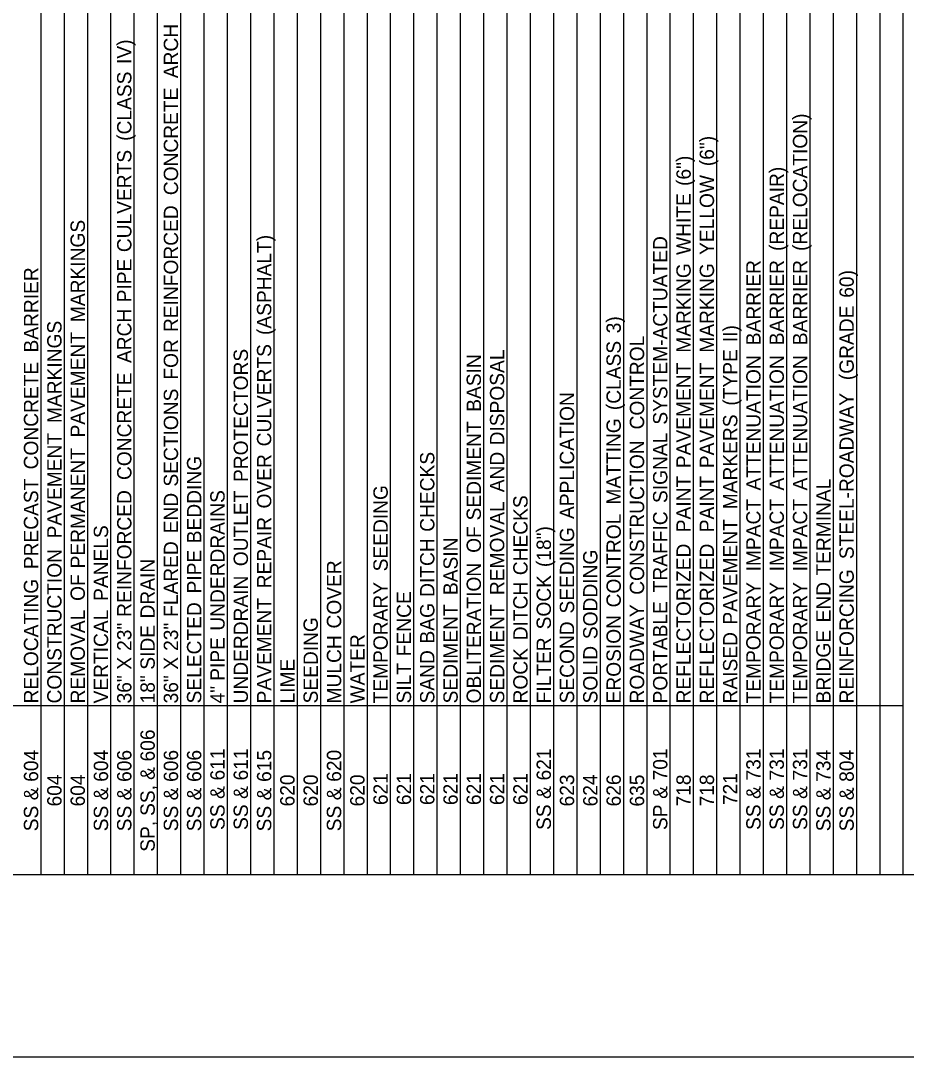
# Model space of a CAD drawing. Extents: x 1334737.6 to 1334769.2, y 402732.2 to 402752.
# Drawn here: x 1334746.86 to 1334756.13, y 402732.19 to 402743.03 of the extents above; entities that cross this region are included whole.
import ezdxf

# ---------------------------------------------------------------- set-up
doc = ezdxf.new("R2010")
doc.units = 0
doc.layers.add('Default', color=7, linetype='Continuous')
doc.layers.add('R_No Plot', color=7, linetype='Continuous')

msp = doc.modelspace()

# ---------------------------------------------------------------- linework, layer by layer
at = {"layer": 'Default'}
for p, q in [((1334747.077, 402734.097), (1334747.077, 402750.83)), ((1334747.321, 402734.097), (1334747.321, 402750.83)), ((1334747.565, 402734.097), (1334747.565, 402750.83)), ((1334747.808, 402734.097), (1334747.808, 402750.83)), ((1334748.052, 402734.097), (1334748.052, 402750.83)), ((1334748.296, 402734.097), (1334748.296, 402750.83)), ((1334748.54, 402734.097), (1334748.54, 402750.83)), ((1334748.783, 402734.097), (1334748.783, 402750.83)), ((1334749.027, 402734.097), (1334749.027, 402750.83)), ((1334749.271, 402734.097), (1334749.271, 402750.83)), ((1334749.515, 402734.097), (1334749.515, 402750.83)), ((1334749.758, 402734.097), (1334749.758, 402750.83)), ((1334750.002, 402734.097), (1334750.002, 402750.83)), ((1334750.246, 402734.097), (1334750.246, 402750.83)), ((1334750.49, 402734.097), (1334750.49, 402750.83)), ((1334750.733, 402734.097), (1334750.733, 402750.83)), ((1334750.977, 402734.097), (1334750.977, 402750.83)), ((1334751.221, 402734.097), (1334751.221, 402750.83)), ((1334751.465, 402734.097), (1334751.465, 402750.83)), ((1334751.708, 402734.097), (1334751.708, 402750.83)), ((1334751.952, 402734.097), (1334751.952, 402750.83)), ((1334752.196, 402734.097), (1334752.196, 402750.83)), ((1334752.44, 402734.097), (1334752.44, 402750.83)), ((1334752.683, 402734.097), (1334752.683, 402750.83)), ((1334752.927, 402734.097), (1334752.927, 402750.83)), ((1334753.171, 402734.097), (1334753.171, 402750.83)), ((1334753.415, 402734.097), (1334753.415, 402750.83)), ((1334753.658, 402734.097), (1334753.658, 402750.83)), ((1334753.902, 402734.097), (1334753.902, 402750.83)), ((1334754.146, 402734.097), (1334754.146, 402750.83)), ((1334754.39, 402734.097), (1334754.39, 402750.83)), ((1334754.633, 402734.097), (1334754.633, 402750.83)), ((1334754.877, 402734.097), (1334754.877, 402750.83)), ((1334755.121, 402734.097), (1334755.121, 402750.83)), ((1334755.365, 402734.097), (1334755.365, 402750.83)), ((1334755.608, 402734.097), (1334755.608, 402750.83)), ((1334755.852, 402734.097), (1334755.852, 402750.83)), ((1334756.096, 402734.097), (1334756.096, 402750.83)), ((1334756.096, 402735.864), (1334740.008, 402735.864)), ((1334756.096, 402735.864), (1334755.608, 402735.864)), ((1334761.215, 402734.097), (1334740.008, 402734.097))]:
    msp.add_line(p, q, dxfattribs=at)
at = {"layer": 'R_No Plot'}
msp.add_line((1334769.182, 402732.187), (1334737.564, 402732.187), dxfattribs=at)

# ---------------------------------------------------------------- texts
at = {"layer": 'Default'}
for s, p in [(' ARCH', (1334748.51, 402742.375)), (' IV)', (1334748.022, 402742.524)), (' (CLASS', (1334748.022, 402741.72)), (' CONCRETE', (1334748.51, 402741.151)), (' (RELOCATION)', (1334755.091, 402740.568)), (' (6")', (1334754.116, 402741.455)), (' CULVERTS', (1334748.022, 402740.555)), (' (6")', (1334753.872, 402741.248)), (' YELLOW', (1334754.116, 402740.526)), (' (REPAIR)', (1334754.847, 402740.568)), (' WHITE', (1334753.872, 402740.526)), (' REINFORCED', (1334748.51, 402739.719)), (' MARKINGS', (1334747.535, 402739.823)), (' (ASPHALT)', (1334749.485, 402739.688)), (' SYSTEM-ACTUATED', (1334753.628, 402738.75)), (' PIPE', (1334748.022, 402740.03)), (' BARRIER', (1334747.047, 402739.505)), (' MARKING', (1334753.872, 402739.503)), (' MARKING', (1334754.116, 402739.503)), (' BARRIER', (1334754.603, 402739.581)), (' BARRIER', (1334754.847, 402739.581)), (' BARRIER', (1334755.091, 402739.581)), (' 60)', (1334755.578, 402740.078)), (' ARCH', (1334748.022, 402739.395)), (' (GRADE', (1334755.578, 402739.216)), (' MARKINGS', (1334747.291, 402738.767)), (' 3)', (1334753.141, 402739.706)), (' PAVEMENT', (1334747.535, 402738.616)), (' II)', (1334754.36, 402739.613)), (' FOR', (1334748.51, 402739.221)), (' (CLASS', (1334753.141, 402738.902)), (' CONTROL', (1334753.385, 402738.7)), (' PROTECTORS', (1334749.241, 402738.15)), (' CULVERTS', (1334749.485, 402738.523)), (' DISPOSAL', (1334751.922, 402738.533)), (' (TYPE', (1334754.36, 402738.949)), (' CONCRETE', (1334747.047, 402738.282)), (' BASIN', (1334751.678, 402738.885)), (' PAVEMENT', (1334753.872, 402738.295)), (' PAVEMENT', (1334754.116, 402738.295)), (' ATTENUATION', (1334754.603, 402738.061)), (' ATTENUATION', (1334754.847, 402738.061)), (' ATTENUATION', (1334755.091, 402738.061)), (' CONCRETE', (1334748.022, 402738.171)), (' SECTIONS', (1334748.51, 402738.102)), (' APPLICATION', (1334752.653, 402737.763)), (' STEEL-ROADWAY', (1334755.578, 402737.343)), (' MARKERS', (1334754.36, 402737.865)), (' SEDIMENT', (1334751.678, 402737.748)), (' MATTING', (1334753.141, 402737.914)), (' PAVEMENT', (1334747.291, 402737.56)), (' SIGNAL', (1334753.628, 402737.93)), (' CONSTRUCTION', (1334753.385, 402736.97)), (' PERMANENT', (1334747.535, 402737.246)), (' BEDDING', (1334748.753, 402737.509)), (' OVER', (1334749.485, 402737.873)), (' CHECKS', (1334751.191, 402737.629)), (' AND', (1334751.922, 402738.043)), (' PAINT', (1334753.872, 402737.624)), (' PAINT', (1334754.116, 402737.624)), (' PRECAST', (1334747.047, 402737.238)), (' SEEDING', (1334750.703, 402737.215)), (' TERMINAL', (1334755.335, 402737.171)), (' REINFORCED', (1334748.022, 402736.739)), (' END', (1334748.51, 402737.613)), (' UNDERDRAINS', (1334748.997, 402736.594)), (' OUTLET', (1334749.241, 402737.269)), (' CHECKS', (1334752.166, 402737.175)), (' REMOVAL', (1334751.922, 402736.967)), (' IMPACT', (1334754.603, 402737.215)), (' IMPACT', (1334754.847, 402737.215)), (' IMPACT', (1334755.091, 402737.215)), (' REPAIR', (1334749.485, 402737.038)), (' CONTROL', (1334753.141, 402736.838)), (' TRAFFIC', (1334753.628, 402736.996)), (' PAVEMENT', (1334754.36, 402736.658)), (' PANELS', (1334747.778, 402736.906)), (' OF', (1334751.678, 402737.409)), (' (18")', (1334752.41, 402737.26)), (' SEEDING', (1334752.653, 402736.774)), (' DITCH', (1334751.191, 402736.948)), (' BASIN', (1334751.435, 402736.967)), ('CONSTRUCTION', (1334747.291, 402735.889)), (' FLARED', (1334748.51, 402736.739)), (' PIPE', (1334748.753, 402736.984)), ('REFLECTORIZED', (1334753.872, 402735.889)), ('REFLECTORIZED', (1334754.116, 402735.889)), (' DRAIN', (1334748.266, 402736.722)), (' SODDING', (1334752.897, 402736.506)), (' COVER', (1334750.216, 402736.617)), ('OBLITERATION', (1334751.678, 402735.889)), ('REINFORCING', (1334755.578, 402735.889)), ('RELOCATING', (1334747.047, 402735.889)), (' OF', (1334747.535, 402736.906)), ('UNDERDRAIN', (1334749.241, 402735.889)), (' SOCK', (1334752.41, 402736.608)), ('TEMPORARY', (1334750.703, 402735.889)), (' FENCE', (1334750.947, 402736.327)), (' DITCH', (1334752.166, 402736.494)), ('TEMPORARY', (1334754.603, 402735.889)), ('TEMPORARY', (1334754.847, 402735.889)), ('TEMPORARY', (1334755.091, 402735.889)), (' END', (1334755.335, 402736.681)), ('PAVEMENT', (1334749.485, 402735.889)), ('PORTABLE', (1334753.628, 402735.889)), ('REMOVAL', (1334747.535, 402735.889)), ('VERTICAL', (1334747.778, 402735.889)), ('SELECTED', (1334748.753, 402735.889)), (' BAG', (1334751.191, 402736.46)), ('SEDIMENT', (1334751.435, 402735.889)), ('SEDIMENT', (1334751.922, 402735.889)), ('ROADWAY', (1334753.385, 402735.889)), ('SEEDING', (1334749.972, 402735.889)), ('SECOND', (1334752.653, 402735.889)), ('EROSION', (1334753.141, 402735.889)), (' 23"', (1334748.022, 402736.383)), (' SIDE', (1334748.266, 402736.186)), (' 23"', (1334748.51, 402736.383)), ('RAISED', (1334754.36, 402735.889)), ('BRIDGE', (1334755.335, 402735.889)), (' PIPE', (1334748.997, 402736.07)), ('MULCH', (1334750.216, 402735.889)), ('WATER', (1334750.46, 402735.889)), ('FILTER', (1334752.41, 402735.889)), ('SAND', (1334751.191, 402735.889)), ('ROCK', (1334752.166, 402735.889)), ('SOLID', (1334752.897, 402735.889)), (' X', (1334748.022, 402736.186)), (' X', (1334748.51, 402736.186)), ('LIME', (1334749.728, 402735.889)), ('SILT', (1334750.947, 402735.889)), ('36"', (1334748.022, 402735.889)), ('18"', (1334748.266, 402735.889)), ('36"', (1334748.51, 402735.889)), ('4"', (1334748.997, 402735.889)), (' 606', (1334748.266, 402735.226)), (' 604', (1334747.047, 402735.013)), (' 604', (1334747.778, 402735.013)), (' 606', (1334748.022, 402735.012)), (' 606', (1334748.51, 402735.012)), (' 606', (1334748.753, 402735.012)), (' 611', (1334748.997, 402735.027)), (' 611', (1334749.241, 402735.027)), (' 615', (1334749.485, 402735.012)), (' 620', (1334750.216, 402735.013)), (' 621', (1334752.41, 402735.027)), (' 701', (1334753.628, 402735.028)), (' 731', (1334754.603, 402735.027)), (' 731', (1334754.847, 402735.027)), (' 731', (1334755.091, 402735.027)), (' 734', (1334755.335, 402735.013)), (' 804', (1334755.578, 402735.013)), (' &', (1334748.266, 402735.033)), ('604', (1334747.291, 402734.811)), ('604', (1334747.535, 402734.811)), ('620', (1334749.728, 402734.811)), ('620', (1334749.972, 402734.811)), ('620', (1334750.46, 402734.811)), ('621', (1334750.703, 402734.825)), ('621', (1334750.947, 402734.825)), ('621', (1334751.191, 402734.825)), ('621', (1334751.435, 402734.825)), ('621', (1334751.678, 402734.825)), ('621', (1334751.922, 402734.825)), ('621', (1334752.166, 402734.825)), ('623', (1334752.653, 402734.811)), ('624', (1334752.897, 402734.811)), ('626', (1334753.141, 402734.811)), ('635', (1334753.385, 402734.81)), ('718', (1334753.872, 402734.811)), ('718', (1334754.116, 402734.811)), ('721', (1334754.36, 402734.825)), (' &', (1334747.047, 402734.82)), (' &', (1334747.778, 402734.82)), (' &', (1334748.022, 402734.819)), (' SS,', (1334748.266, 402734.656)), (' &', (1334748.51, 402734.819)), (' &', (1334748.753, 402734.819)), (' &', (1334748.997, 402734.834)), (' &', (1334749.241, 402734.834)), (' &', (1334749.485, 402734.819)), (' &', (1334750.216, 402734.82)), (' &', (1334752.41, 402734.834)), (' &', (1334753.628, 402734.835)), (' &', (1334754.603, 402734.834)), (' &', (1334754.847, 402734.834)), (' &', (1334755.091, 402734.834)), (' &', (1334755.335, 402734.82)), (' &', (1334755.578, 402734.82)), ('SS', (1334747.047, 402734.551)), ('SS', (1334747.778, 402734.551)), ('SS', (1334748.022, 402734.551)), ('SS', (1334748.51, 402734.551)), ('SS', (1334748.753, 402734.551)), ('SS', (1334748.997, 402734.565)), ('SS', (1334749.241, 402734.565)), ('SS', (1334749.485, 402734.55)), ('SS', (1334750.216, 402734.551)), ('SS', (1334752.41, 402734.565)), ('SP', (1334753.628, 402734.564)), ('SS', (1334754.603, 402734.565)), ('SS', (1334754.847, 402734.565)), ('SS', (1334755.091, 402734.565)), ('SS', (1334755.335, 402734.551)), ('SS', (1334755.578, 402734.551)), ('SP,', (1334748.266, 402734.337))]:
    msp.add_text(s, height=0.15, rotation=90, dxfattribs=at).set_placement(p)

doc.saveas('drawing.dxf')
